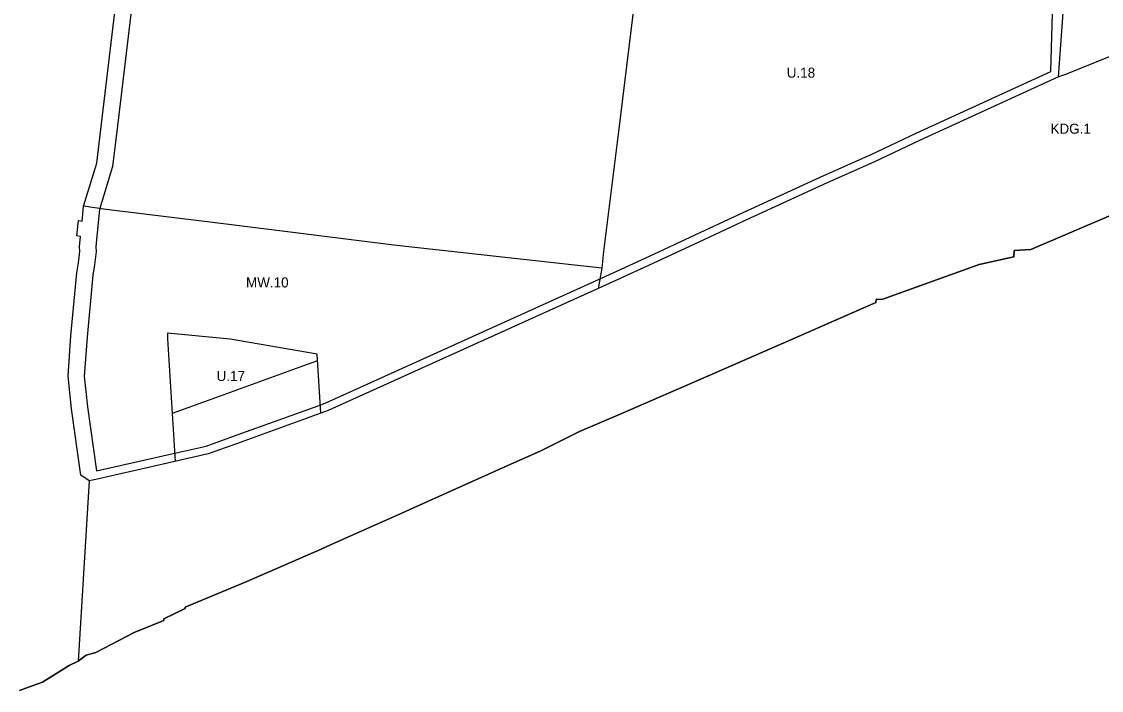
# Model space of a CAD drawing. Extents: x 7428112 to 7429828, y 5548245 to 5549272.
# Drawn here: x 7428737 to 7429274, y 5548308 to 5548641 of the extents above; entities that cross this region are included whole.
import ezdxf

# ---------------------------------------------------------------- set-up
doc = ezdxf.new("R2010")
doc.units = 0
for name, color, linetype in [('LIN_granica_planu', 7, 'Continuous'), ('LIN_Linia Zabudowy Nieprzekraczalna', 7, 'Continuous'), ('LIN_linie_rozgraniczajace', 7, 'Continuous'), ('TXT_oznaczenia_przeznaczen', 7, 'Continuous')]:
    doc.layers.add(name, color=color, linetype=linetype)

msp = doc.modelspace()

# ---------------------------------------------------------------- linework, layer by layer
at = {"layer": 'LIN_granica_planu'}
msp.add_lwpolyline([(7429277.79, 5548543.89), (7429238.95, 5548527.29), (7429230.63, 5548526.88), (7429230.61, 5548523.64), (7429213.25, 5548519.88), (7429165.49, 5548502.58), (7429162.04, 5548502.51), (7429161.85, 5548500.96), (7429123.85, 5548484.23), (7429079.08, 5548464.72), (7429034.74, 5548445.41), (7429014.61, 5548436.76), (7428995.01, 5548427), (7428981.98, 5548421.2), (7428977.48, 5548419.2), (7428932.1, 5548398.91), (7428926.62, 5548396.46), (7428890.75, 5548380.42), (7428886.16, 5548378.42), (7428849.11, 5548362.29), (7428818.48, 5548349.44), (7428818.52, 5548348.88), (7428807.98, 5548343.65), (7428807.99, 5548342.84), (7428793.12, 5548336.99), (7428774.15, 5548326.9), (7428769.34, 5548325.6), (7428765.26, 5548322.63), (7428760.77, 5548320.46), (7428747.59, 5548312.24), (7428742.91, 5548310.54), (7428736.09, 5548308.14)], dxfattribs=at)
at = {"layer": 'LIN_Linia Zabudowy Nieprzekraczalna'}
for points in [[(7428774.42, 5548417.21), (7428812.54, 5548425.84), (7428828.9, 5548429.55), (7428842.63, 5548434.5), (7428884.58, 5548449.65), (7428888.08, 5548450.92), (7429022.28, 5548511.56), (7429031.26, 5548515.69), (7429049.34, 5548523.98), (7429074.66, 5548535.74), (7429095.96, 5548545.64), (7429136.13, 5548564.02), (7429159.53, 5548574.44), (7429182.02, 5548585.16), (7429248.89, 5548615.78), (7429250.64, 5548673.83)], [(7428793.64, 5548662.49), (7428784.91, 5548588.83), (7428782.41, 5548568.61), (7428775.94, 5548547.19), (7428775.27, 5548540.64), (7428775.27, 5548540.64), (7428774.05, 5548528.63), (7428774.24, 5548526.37), (7428773.4, 5548519.61), (7428772.61, 5548514.62), (7428769.72, 5548483.71), (7428768.38, 5548464.42), (7428769.9, 5548449.09), (7428774.42, 5548417.21)], [(7428884.38, 5548471.91), (7428877.44, 5548469.4), (7428835.5, 5548454.25), (7428812.05, 5548445.79)]]:
    msp.add_lwpolyline(points, dxfattribs=at)
at = {"layer": 'LIN_linie_rozgraniczajace'}
for p, q in [((7429025.62, 5548517.96), (7429023.94, 5548507.92)), ((7428840.88, 5548482.65), (7428809.66, 5548485.65)), ((7428809.66, 5548485.65), (7428809.82, 5548482.84)), ((7428809.82, 5548482.84), (7428813.48, 5548421.95)), ((7428884.17, 5548475.34), (7428840.88, 5548482.65)), ((7428885.94, 5548445.89), (7428884.17, 5548475.34)), ((7428885.94, 5548445.89), (7428885.94, 5548445.89)), ((7428770.8, 5548412.3), (7428765.26, 5548322.63))]:
    msp.add_line(p, q, dxfattribs=at)
for points in [[(7429252.81, 5548613.18), (7429256.65, 5548667.75), (7429263.83, 5548682.83), (7429268.74, 5548693.16), (7429271.85, 5548699.71), (7429272.91, 5548708.97), (7429272.01, 5548725.58), (7429270.69, 5548733.9), (7429264.62, 5548751.1), (7429257.96, 5548768.42), (7429251.81, 5548785.28), (7429245.66, 5548802.14), (7429239.47, 5548819.12), (7429233.47, 5548835.9), (7429227.3, 5548852.67), (7429220.67, 5548871.39), (7429213.88, 5548890.76), (7429212.38, 5548895.58), (7429214.64, 5548899.71), (7429218.01, 5548905.33), (7429224.07, 5548909.19), (7429248.15, 5548917.56), (7429264.13, 5548923.82)], [(7428770.8, 5548412.3), (7428766.64, 5548415.11), (7428761.95, 5548448.13), (7428760.36, 5548464.3), (7428761.75, 5548484.36), (7428764.67, 5548515.63), (7428765.48, 5548520.73), (7428766.2, 5548526.53), (7428766.02, 5548528.7), (7428766.54, 5548533.82), (7428764.74, 5548534.08), (7428765.44, 5548541.68), (7428767.31, 5548541.41), (7428768.06, 5548548.77), (7428774.55, 5548570.27), (7428776.97, 5548589.79), (7428785.7, 5548663.43), (7428794.62, 5548738.74)], [(7429049.66, 5548719.76), (7429048.89, 5548710.74), (7429044.7, 5548673.94), (7429042.94, 5548659.17), (7429034.04, 5548585.96), (7429026.55, 5548526.32), (7429025.62, 5548517.96), (7429007.68, 5548519.94), (7428922.28, 5548529.44), (7428845.59, 5548539.14), (7428829.43, 5548541.08), (7428779.2, 5548547.16), (7428768.06, 5548548.76)], [(7429280.37, 5548624.1), (7429256.15, 5548614.36), (7429252.81, 5548613.18), (7429183.71, 5548581.54), (7429161.21, 5548570.81), (7429137.78, 5548560.37), (7429097.64, 5548542.01), (7429076.35, 5548532.11), (7429051.02, 5548520.35), (7429032.93, 5548512.05), (7429023.94, 5548507.92), (7428889.59, 5548447.21), (7428885.94, 5548445.89), (7428843.99, 5548430.74), (7428830.02, 5548425.7), (7428813.42, 5548421.94), (7428774.15, 5548413.05), (7428770.8, 5548412.3)], [(7428736.09, 5548308.14), (7428742.91, 5548310.54), (7428747.59, 5548312.24), (7428760.77, 5548320.46), (7428765.26, 5548322.63), (7428769.34, 5548325.6), (7428774.15, 5548326.9), (7428793.12, 5548336.99), (7428807.99, 5548342.84), (7428807.98, 5548343.65), (7428818.52, 5548348.88), (7428818.48, 5548349.44), (7428849.11, 5548362.29), (7428886.16, 5548378.42), (7428890.75, 5548380.42), (7428926.62, 5548396.46), (7428932.1, 5548398.91), (7428977.48, 5548419.2), (7428981.98, 5548421.2), (7428995.01, 5548427), (7429014.61, 5548436.76), (7429034.74, 5548445.41), (7429079.08, 5548464.72), (7429123.85, 5548484.23), (7429161.85, 5548500.96), (7429162.04, 5548502.51), (7429165.49, 5548502.58), (7429213.25, 5548519.88), (7429230.61, 5548523.64), (7429230.63, 5548526.88), (7429238.95, 5548527.29), (7429277.79, 5548543.89)]]:
    msp.add_lwpolyline(points, dxfattribs=at)

# ---------------------------------------------------------------- texts
at = {"layer": 'TXT_oznaczenia_przeznaczen'}
for s, p in [('U.18', (7429117.64, 5548612.69)), ('KDG.1', (7429248.78, 5548584.85)), ('MW.10', (7428848.79, 5548508.43)), ('U.17', (7428834.15, 5548461.93))]:
    msp.add_text(s, height=5, dxfattribs=at).set_placement(p)

doc.saveas('drawing.dxf')
